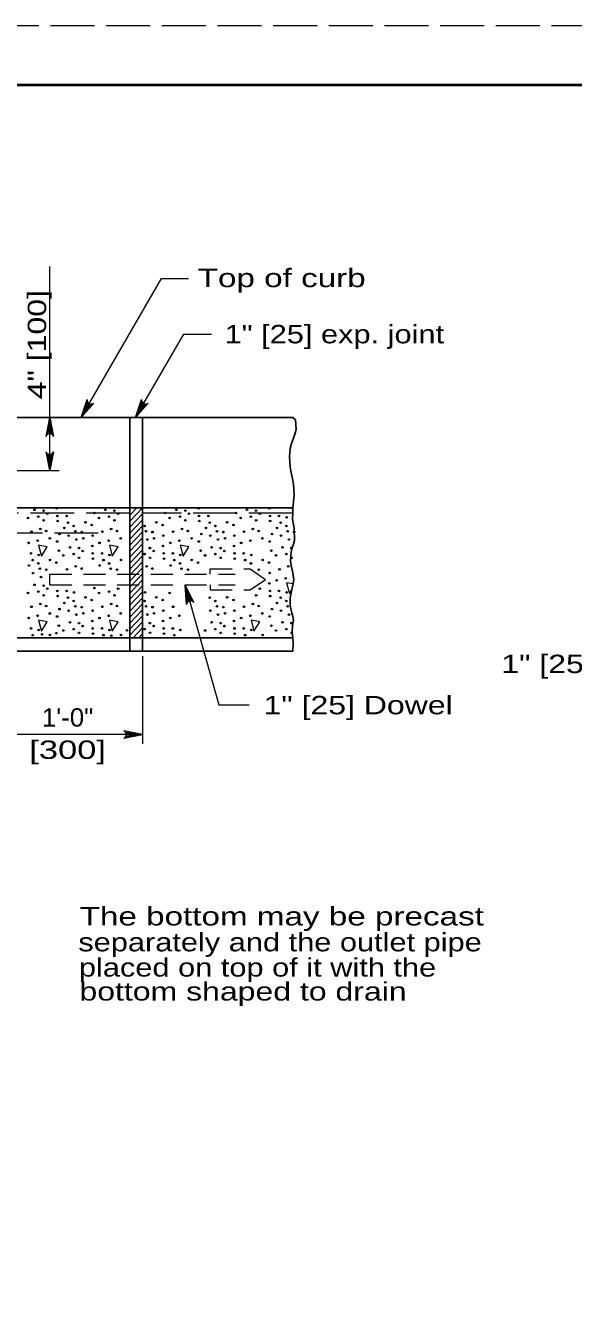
# Model space of a CAD drawing. Extents: x 1352.5 to 1386.5, y 735.9 to 779.9.
# Drawn here: x 1367.52 to 1372.16, y 768.97 to 779.92 of the extents above; entities that cross this region are included whole.
import ezdxf
from ezdxf.enums import TextEntityAlignment as Align

# ---------------------------------------------------------------- set-up
doc = ezdxf.new("R2010")
doc.units = 0
doc.header["$LTSCALE"] = 0.062
doc.linetypes.add('LONG_DASHED', pattern=[7.5, 6, -1.5])
doc.linetypes.add('MEDIUM_DASHED', pattern=[4.5, 3, -1.5])
doc.layers.add('1', color=7, linetype='Continuous', lineweight=13)

msp = doc.modelspace()

# ---------------------------------------------------------------- linework, layer by layer
at = {"layer": '1', "lineweight": 25}
for p, q in [((1354.513, 779.41967), (1386.013, 779.41967)), ((1356.99975, 776.599), (1369.78625, 776.599)), ((1368.51183, 776.599), (1368.51183, 774.62017)), ((1368.40567, 775.83442), (1366.664, 775.83442)), ((1368.40567, 774.62017), (1367.21625, 774.62017))]:
    msp.add_line(p, q, dxfattribs=at)
at = {"layer": '1'}
for p, q in [((1367.99175, 776.599), (1368.673, 777.779)), ((1368.673, 777.779), (1368.90225, 777.779)), ((1368.45275, 776.59925), (1368.86133, 777.307)), ((1368.86133, 777.307), (1369.09608, 777.307)), ((1368.04558, 776.73433), (1367.99175, 776.599)), ((1368.05183, 776.72517), (1367.99175, 776.599)), ((1368.05992, 776.71883), (1367.99175, 776.599)), ((1368.08333, 776.71483), (1367.99175, 776.599)), ((1368.07242, 776.71467), (1367.99175, 776.599)), ((1368.50758, 776.73417), (1368.45275, 776.59925)), ((1368.51375, 776.72492), (1368.45275, 776.59925)), ((1368.52183, 776.7185), (1368.45275, 776.59925)), ((1368.54517, 776.71433), (1368.45275, 776.59925)), ((1368.53433, 776.71425), (1368.45275, 776.59925)), ((1367.70367, 776.45308), (1367.726, 776.599)), ((1367.713, 776.45858), (1367.726, 776.599)), ((1367.726, 776.46117), (1367.726, 776.599)), ((1367.73617, 776.45967), (1367.726, 776.599)), ((1367.74617, 776.45475), (1367.726, 776.599)), ((1367.70583, 776.2935), (1367.726, 776.14925)), ((1367.71575, 776.28858), (1367.726, 776.14925)), ((1367.74825, 776.29517), (1367.726, 776.14925)), ((1367.73892, 776.28967), (1367.726, 776.14925)), ((1367.726, 776.28708), (1367.726, 776.14925)), ((1368.40567, 775.77175), (1368.46492, 775.83442)), ((1368.51183, 775.83442), (1368.40567, 775.83442)), ((1368.40567, 775.72083), (1368.51183, 775.83333)), ((1368.40567, 775.67), (1368.51183, 775.78242)), ((1369.78625, 775.82492), (1369.73758, 775.83442)), ((1368.40567, 775.61908), (1368.51183, 775.7315)), ((1368.40567, 775.56817), (1368.51183, 775.68067)), ((1368.40558, 775.51725), (1368.51183, 775.62983)), ((1368.40567, 775.46642), (1368.51183, 775.57892)), ((1368.40567, 775.4155), (1368.51183, 775.528)), ((1368.40567, 775.36467), (1368.51183, 775.47717)), ((1368.40567, 775.31383), (1368.51183, 775.42625)), ((1368.40567, 775.26292), (1368.51183, 775.37533)), ((1368.40567, 775.212), (1368.51183, 775.3245)), ((1368.40567, 775.16108), (1368.51183, 775.27358)), ((1368.40567, 775.11025), (1368.51183, 775.22275)), ((1368.40567, 775.05942), (1368.51183, 775.17183)), ((1368.91042, 775.04383), (1368.87517, 775.17708)), ((1368.8985, 775.03808), (1368.87517, 775.17708)), ((1368.89092, 775.03033), (1368.87517, 775.17708)), ((1368.92067, 775.045), (1368.87517, 775.17708)), ((1368.9315, 775.04283), (1368.87517, 775.17708)), ((1369.78892, 775.18842), (1369.73358, 775.19917)), ((1368.40567, 775.0085), (1368.51183, 775.12092)), ((1368.40567, 774.95758), (1368.51183, 775.07)), ((1368.40567, 774.90667), (1368.51183, 775.01925)), ((1368.40567, 774.85583), (1368.51183, 774.96833)), ((1368.40567, 774.805), (1368.51183, 774.91742)), ((1368.40567, 774.75408), (1368.51183, 774.8665)), ((1368.43333, 774.73258), (1368.51183, 774.81567)), ((1368.48142, 774.73258), (1368.51183, 774.76483)), ((1368.51183, 774.57517), (1368.51183, 773.8335)), ((1368.36767, 773.93233), (1368.51183, 773.91217)), ((1368.3725, 773.92233), (1368.51183, 773.91217)), ((1368.51183, 773.91217), (1367.21625, 773.91217)), ((1368.36592, 773.88983), (1368.51183, 773.91217)), ((1368.3715, 773.89917), (1368.51183, 773.91217)), ((1368.374, 773.91217), (1368.51183, 773.91217))]:
    msp.add_line(p, q, dxfattribs=at)
at = {"layer": '1', "linetype": 'LONG_DASHED'}
for p, q in [((1368.40567, 775.7895), (1366.664, 775.7895)), ((1369.78625, 775.7895), (1368.51183, 775.7895)), ((1368.13708, 775.61933), (1366.88525, 775.61817))]:
    msp.add_line(p, q, dxfattribs=at)
at = {"layer": '1', "linetype": 'MEDIUM_DASHED'}
for p, q in [((1367.726, 775.27225), (1369.29775, 775.27225)), ((1367.726, 775.18233), (1367.726, 775.27225)), ((1367.726, 775.18233), (1369.29775, 775.18233)), ((1369.08533, 775.18233), (1369.08533, 775.13733)), ((1369.08533, 775.13733), (1369.42517, 775.13733)), ((1369.42517, 775.13733), (1369.55392, 775.22733))]:
    msp.add_line(p, q, dxfattribs=at)
at = {"layer": '1', "linetype": 'LONG_DASHED'}
msp.add_lwpolyline([(1352.513, 757.91967), (1386.513, 757.91967), (1386.513, 779.91967), (1352.513, 779.91967)], close=True, dxfattribs=at)
at = {"layer": '1', "lineweight": 40}
msp.add_lwpolyline([(1354.513, 779.41967), (1386.013, 779.41967), (1386.013, 758.41967), (1354.513, 758.41967)], close=True, dxfattribs=at)
msp.add_lwpolyline([(1354.513, 779.41967), (1386.013, 779.41967), (1386.013, 758.41967), (1354.513, 758.41967)], close=True, dxfattribs=at)
at = {"layer": '1'}
for points in [[(1367.726, 776.14925), (1367.726, 776.387), (1367.726, 777.87883)], [(1368.09825, 776.72167), (1367.99175, 776.599), (1368.04283, 776.75325)], [(1368.56017, 776.72108), (1368.45275, 776.59925), (1368.505, 776.75308)], [(1367.69408, 776.43975), (1367.726, 776.599), (1367.75783, 776.43975)], [(1367.75783, 776.30858), (1367.726, 776.14925), (1367.69408, 776.30858)], [(1367.25867, 776.14925), (1367.61683, 776.14925), (1367.80467, 776.14925)], [(1368.88508, 775.01492), (1368.87517, 775.17708), (1368.94667, 775.03125)], [(1368.87517, 775.17708), (1369.15817, 774.16258), (1369.41792, 774.16258)], [(1369.73358, 775.19917), (1369.75783, 775.107), (1369.77758, 775.13825)], [(1368.35258, 773.88025), (1368.51183, 773.91217), (1368.35258, 773.944)]]:
    msp.add_lwpolyline(points, dxfattribs=at)
at = {"layer": '1', "lineweight": 25}
for points in [[(1368.40567, 776.599), (1368.40567, 774.73258), (1368.40567, 774.62017)], [(1369.78625, 776.599), (1369.81067, 776.57875), (1369.81308, 776.54342), (1369.8155, 776.50042), (1369.81067, 776.47517), (1369.79167, 776.42467), (1369.77492, 776.37925), (1369.763, 776.33625), (1369.75825, 776.26558), (1369.76533, 776.17967), (1369.77017, 776.14683), (1369.78208, 776.09383), (1369.794, 776.03325), (1369.79875, 775.93725), (1369.78625, 775.83442)], [(1369.78625, 774.73258), (1369.78208, 774.7805), (1369.7845, 774.83608), (1369.79167, 774.8815), (1369.78683, 774.91183), (1369.77733, 774.94467), (1369.77017, 774.9775), (1369.763, 775.01283), (1369.76533, 775.07092), (1369.77492, 775.1265), (1369.78683, 775.177), (1369.79642, 775.2275), (1369.7845, 775.30075), (1369.77492, 775.32858), (1369.76775, 775.38167), (1369.77017, 775.43717), (1369.77967, 775.48767), (1369.79167, 775.52558), (1369.80117, 775.55583), (1369.80117, 775.58867), (1369.79875, 775.62917), (1369.79875, 775.662), (1369.794, 775.68975), (1369.7845, 775.73767), (1369.78625, 775.7895), (1369.78625, 775.83442), (1368.51183, 775.83442)], [(1358.38042, 774.73258), (1359.56983, 774.73258), (1359.56983, 770.66242), (1367.21625, 770.66242), (1367.21625, 774.73258), (1368.40567, 774.73258), (1369.78625, 774.73258)], [(1369.78625, 774.73258), (1369.78925, 774.6845), (1369.78625, 774.62017)], [(1368.40567, 774.62017), (1368.51183, 774.62017), (1369.78625, 774.62017)]]:
    msp.add_lwpolyline(points, dxfattribs=at)
msp.add_lwpolyline([(1368.40567, 774.73258), (1368.40567, 775.83442), (1368.51183, 775.83442), (1368.51183, 774.73258)], close=True, dxfattribs=at)
at = {"layer": '1'}
for points in [[(1367.63092, 775.51725), (1367.65517, 775.425), (1367.70467, 775.50283)], [(1368.23167, 775.51725), (1368.256, 775.425), (1368.30542, 775.50283)], [(1368.83242, 775.51725), (1368.85675, 775.425), (1368.90617, 775.50283)], [(1367.63092, 774.88117), (1367.65517, 774.789), (1367.70467, 774.86683)], [(1368.23167, 774.88117), (1368.256, 774.789), (1368.30542, 774.86683)], [(1369.43317, 774.88117), (1369.4575, 774.789), (1369.50692, 774.86683)]]:
    msp.add_lwpolyline(points, close=True, dxfattribs=at)
at = {"layer": '1', "linetype": 'MEDIUM_DASHED'}
msp.add_lwpolyline([(1369.08533, 775.27225), (1369.08533, 775.31725), (1369.42517, 775.31725), (1369.55392, 775.22733)], dxfattribs=at)
at = {"layer": '1'}
for centre, start, end in [((1368.07688, 776.74866), 172.44615, 308.27227), ((1368.539, 776.74823), 172.00749, 307.83362), ((1367.72601, 776.42684), 22.08782, 157.91395), ((1367.72594, 776.32143), 202.08782, 337.91395), ((1368.91921, 775.01066), 36.90645, 172.73257), ((1368.33969, 773.91218), 292.08605, 67.91218)]:
    msp.add_arc(centre, 0.03438, start, end, dxfattribs=at)
for centre in [(1367.59662, 775.81688), (1367.67317, 775.81026), (1367.70506, 775.78508), (1367.78536, 775.82886), (1368.10331, 775.78938), (1368.19738, 775.81688), (1368.27392, 775.81026), (1368.30581, 775.78508), (1368.70407, 775.78938), (1368.79814, 775.81688), (1368.87468, 775.81026), (1368.90657, 775.78508), (1368.98687, 775.82886), (1369.30482, 775.78938), (1369.39889, 775.81688), (1369.47544, 775.81026), (1369.50733, 775.78508), (1369.58763, 775.82886), (1367.5415, 775.74814), (1367.62826, 775.75932), (1367.67397, 775.7281), (1367.79021, 775.76531), (1367.79262, 775.72153), (1367.86811, 775.76531), (1367.88108, 775.70865), (1367.92889, 775.6803), (1368.02866, 775.71035), (1368.08218, 775.68803), (1368.14226, 775.74814), (1368.22902, 775.75932), (1368.27472, 775.7281), (1368.52965, 775.6803), (1368.62942, 775.71035), (1368.68294, 775.68803), (1368.74302, 775.74814), (1368.82977, 775.75932), (1368.87548, 775.7281), (1368.99173, 775.76531), (1368.99413, 775.72153), (1369.06963, 775.76531), (1369.08259, 775.70865), (1369.1304, 775.6803), (1369.23018, 775.71035), (1369.2837, 775.68803), (1369.34377, 775.74814), (1369.43053, 775.75932), (1369.47624, 775.7281), (1369.59249, 775.76531), (1369.59489, 775.72153), (1369.67039, 775.76531), (1369.68335, 775.70865), (1369.73116, 775.6803), (1369.73442, 775.75243), (1367.57094, 775.63111), (1367.64558, 775.65512), (1367.69504, 775.6371), (1367.72663, 775.5744), (1367.80859, 775.61134), (1367.84939, 775.66312), (1367.88508, 775.59788), (1367.9419, 775.63567), (1367.95157, 775.56523), (1367.99622, 775.62788), (1368.00999, 775.57556), (1368.08869, 775.59867), (1368.17169, 775.63111), (1368.24634, 775.65512), (1368.2958, 775.6371), (1368.32739, 775.5744), (1368.54266, 775.63567), (1368.55232, 775.56523), (1368.59698, 775.62788), (1368.61075, 775.57556), (1368.68945, 775.59867), (1368.77245, 775.63111), (1368.8471, 775.65512), (1368.89656, 775.6371), (1368.92815, 775.5744), (1369.0101, 775.61134), (1369.0509, 775.66312), (1369.0866, 775.59788), (1369.14342, 775.63567), (1369.15308, 775.56523), (1369.19774, 775.62788), (1369.21151, 775.57556), (1369.29021, 775.59867), (1369.37321, 775.63111), (1369.44785, 775.65512), (1369.49732, 775.6371), (1369.52891, 775.5744), (1369.61086, 775.61134), (1369.65166, 775.66312), (1369.68736, 775.59788), (1369.74418, 775.63567), (1369.75384, 775.56523), (1369.7985, 775.62788), (1367.54656, 775.53661), (1367.56773, 775.4473), (1367.62365, 775.55463), (1367.78831, 775.54864), (1367.80293, 775.47136), (1367.897, 775.49887), (1367.97354, 775.49224), (1368.00543, 775.46707), (1368.08574, 775.51085), (1368.09059, 775.4473), (1368.14731, 775.53661), (1368.16849, 775.4473), (1368.22441, 775.55463), (1368.5743, 775.49224), (1368.60619, 775.46707), (1368.68649, 775.51085), (1368.69135, 775.4473), (1368.74807, 775.53661), (1368.76925, 775.4473), (1368.82517, 775.55463), (1368.98983, 775.54864), (1369.00445, 775.47136), (1369.09851, 775.49887), (1369.17506, 775.49224), (1369.20695, 775.46707), (1369.28725, 775.51085), (1369.29211, 775.4473), (1369.34883, 775.53661), (1369.37001, 775.4473), (1369.42593, 775.55463), (1369.59058, 775.54864), (1369.6052, 775.47136), (1369.69927, 775.49887), (1369.77582, 775.49224), (1367.54901, 775.34511), (1367.5807, 775.39064), (1367.62851, 775.36228), (1367.63176, 775.43442), (1367.72829, 775.39233), (1367.7818, 775.37002), (1367.84188, 775.43012), (1367.92864, 775.44131), (1367.94596, 775.33711), (1367.97435, 775.41009), (1368.093, 775.40352), (1368.14977, 775.34511), (1368.18146, 775.39064), (1368.22927, 775.36228), (1368.23252, 775.43442), (1368.32904, 775.39233), (1368.5294, 775.44131), (1368.54672, 775.33711), (1368.5751, 775.41009), (1368.69375, 775.40352), (1368.75053, 775.34511), (1368.78221, 775.39064), (1368.83003, 775.36228), (1368.83328, 775.43442), (1368.9298, 775.39233), (1368.98332, 775.37002), (1369.04339, 775.43012), (1369.13015, 775.44131), (1369.17586, 775.41009), (1369.29451, 775.40352), (1369.38297, 775.39064), (1369.43078, 775.36228), (1369.43404, 775.43442), (1369.53056, 775.39233), (1369.58408, 775.37002), (1369.64415, 775.43012), (1369.73091, 775.44131), (1369.74823, 775.33711), (1369.77662, 775.41009), (1367.5847, 775.27986), (1367.64153, 775.31765), (1367.65119, 775.24721), (1367.69584, 775.30986), (1367.87132, 775.3131), (1367.99542, 775.31908), (1368.24228, 775.31765), (1368.2966, 775.30986), (1368.59618, 775.31908), (1368.84304, 775.31765), (1368.89736, 775.30986), (1369.49812, 775.30986), (1369.59058, 775.28066), (1369.67359, 775.3131), (1369.72631, 775.23661), (1367.59662, 775.18085), (1367.62826, 775.12329), (1367.67317, 775.17423), (1367.70506, 775.14905), (1367.79021, 775.12928), (1367.86811, 775.12928), (1368.10331, 775.15335), (1368.22902, 775.12329), (1368.30581, 775.14905), (1369.50733, 775.14905), (1369.58763, 775.19283), (1369.59249, 775.12928), (1369.64921, 775.21859), (1369.67039, 775.12928), (1367.5415, 775.11211), (1367.64558, 775.01909), (1367.67397, 775.09208), (1367.79262, 775.0855), (1367.84939, 775.02709), (1367.88108, 775.07262), (1367.92889, 775.04427), (1367.93214, 775.1164), (1368.02866, 775.07432), (1368.08218, 775.05201), (1368.14226, 775.11211), (1368.24634, 775.01909), (1368.27472, 775.09208), (1368.52965, 775.04427), (1368.5329, 775.1164), (1368.62942, 775.07432), (1368.68294, 775.05201), (1368.74302, 775.11211), (1369.08259, 775.07262), (1369.1304, 775.04427), (1369.23018, 775.07432), (1369.2837, 775.05201), (1369.44785, 775.01909), (1369.47624, 775.09208), (1369.59489, 775.0855), (1369.65166, 775.02709), (1369.68335, 775.07262), (1369.73116, 775.04427), (1369.73442, 775.1164), (1367.54656, 774.90058), (1367.57094, 774.99508), (1367.62365, 774.9186), (1367.69504, 775.00107), (1367.72663, 774.93837), (1367.78831, 774.91261), (1367.80859, 774.97531), (1367.88508, 774.96185), (1367.9419, 774.99964), (1367.95157, 774.9292), (1367.99622, 774.99185), (1368.00999, 774.93953), (1368.08869, 774.96264), (1368.14731, 774.90058), (1368.17169, 774.99508), (1368.22441, 774.9186), (1368.2958, 775.00107), (1368.32739, 774.93837), (1368.54266, 774.99964), (1368.55232, 774.9292), (1368.59698, 774.99185), (1368.61075, 774.93953), (1368.68945, 774.96264), (1368.74807, 774.90058), (1368.77245, 774.99508), (1368.82517, 774.9186), (1369.0866, 774.96185), (1369.14342, 774.99964), (1369.15308, 774.9292), (1369.19774, 774.99185), (1369.21151, 774.93953), (1369.29021, 774.96264), (1369.34883, 774.90058), (1369.37321, 774.99508), (1369.42593, 774.9186), (1369.49732, 775.00107), (1369.52891, 774.93837), (1369.59058, 774.91261), (1369.61086, 774.97531), (1369.68736, 774.96185), (1369.74418, 774.99964), (1369.75384, 774.9292), (1367.56773, 774.81127), (1367.63176, 774.79839), (1367.80293, 774.83533), (1367.84188, 774.7941), (1367.897, 774.86284), (1367.92864, 774.80528), (1367.97354, 774.85621), (1368.00543, 774.83104), (1368.08574, 774.87482), (1368.09059, 774.81127), (1368.16849, 774.81127), (1368.23252, 774.79839), (1368.38101, 774.79432), (1368.5294, 774.80528), (1368.5743, 774.85621), (1368.60619, 774.83104), (1368.68649, 774.87482), (1368.69135, 774.81127), (1368.76925, 774.81127), (1368.83328, 774.79839), (1369.04339, 774.7941), (1369.09851, 774.86284), (1369.13015, 774.80528), (1369.17506, 774.85621), (1369.20695, 774.83104), (1369.28725, 774.87482), (1369.29211, 774.81127), (1369.37001, 774.81127), (1369.43404, 774.79839), (1369.6052, 774.83533), (1369.64415, 774.7941), (1369.69927, 774.86284), (1369.73091, 774.80528), (1369.77582, 774.85621), (1367.5807, 774.75461), (1367.66098, 774.76183), (1367.72829, 774.7563), (1367.7818, 774.77112), (1367.97435, 774.77406), (1368.093, 774.76749), (1368.18146, 774.75461), (1368.24782, 774.74946), (1368.32904, 774.7563), (1368.5751, 774.77406), (1368.69375, 774.76749), (1368.78221, 774.75461), (1369.17586, 774.77406), (1369.29451, 774.76749), (1369.38297, 774.75461), (1369.53056, 774.7563), (1369.77662, 774.77406)]:
    msp.add_ellipse(centre, major_axis=(0, 0.0068), ratio=0.944544, dxfattribs=at)

# ---------------------------------------------------------------- texts
for s, width, p in [('Top of curb', 1.35, (1368.98033, 777.70458)), ('1" [25] exp. joint', 1.25, (1369.20825, 777.22817)), ('1" [25] Dowel', 1.3, (1371.55483, 774.43267)), ('1" [25] Dowel', 1.3, (1369.53867, 774.08358)), ('The bottom may be precast', 1.35, (1367.97917, 772.29367)), ('separately and the outlet pipe', 1.25, (1367.96792, 772.07417)), ('placed on top of it with the', 1.25, (1367.97292, 771.86008)), ('bottom shaped to drain', 1.3, (1367.97758, 771.65692))]:
    msp.add_text(s, height=0.156, dxfattribs=dict(at, width=width)).set_placement(p)
at = {"layer": '1', "width": 1.3}
msp.add_text('4" [100]', height=0.156, rotation=90, dxfattribs=at).set_placement((1367.69508, 776.754))
at = {"layer": '1'}
for s, width, p in [('1\'-0"', 1.05, (1367.87721, 773.9795)), ('[300]', 1.4, (1367.87725, 773.7055))]:
    msp.add_text(s, height=0.156, dxfattribs=dict(at, width=width)).set_placement(p, align=Align.CENTER)

doc.saveas('drawing.dxf')
